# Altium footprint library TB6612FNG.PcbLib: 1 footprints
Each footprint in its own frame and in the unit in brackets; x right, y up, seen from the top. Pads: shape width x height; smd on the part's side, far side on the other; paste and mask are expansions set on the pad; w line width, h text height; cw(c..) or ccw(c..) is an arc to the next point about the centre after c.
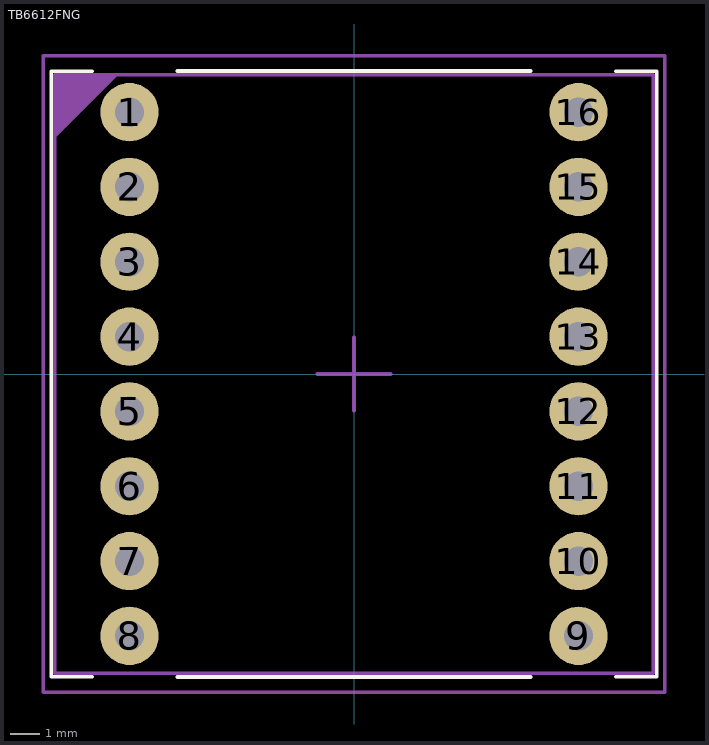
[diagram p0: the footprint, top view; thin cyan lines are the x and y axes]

## TB6612FNG [mm]
pads (16):
  round 1.98 hole 1: 1(-7.62,8.89) 2(-7.62,6.35) 3(-7.62,3.81) 4(-7.62,1.27) 5(-7.62,-1.27) 6(-7.62,-3.81) 7(-7.62,-6.35) 8(-7.62,-8.89) 9(7.62,-8.89) 10(7.62,-6.35) 11(7.62,-3.81) 12(7.62,-1.27) 13(7.62,1.27) 14(7.62,3.81) 15(7.62,6.35) 16(7.62,8.89)
Top Overlay:
  lines w0.127: -8.89,-10.28 -10.275,-10.28 -10.275,10.28 -8.89,10.28 ; -6,-10.285 6,-10.285 ; -6,10.285 6,10.285 ; 8.89,-10.28 10.275,-10.28 10.275,10.28 8.89,10.28
Top Assembly:
  region: -8,10.16 -10.16,10.16 -10.16,8
  lines w0.127: -10.16,-10.16 -10.16,10.16 10.16,10.16 10.16,-10.16 -10.16,-10.16
Top Courtyard (Mech15):
  lines w0.127: -1.25,0 1.25,0 ; 0,-1.25 0,1.25 ; -10.55,-10.8 -10.55,10.8 10.55,10.8 10.55,-10.8 -10.55,-10.8
3D body "TB6612FNG Module.STEP": height 6.12, standoff -5.99, extent -10.452,-10.28 10.452,10.7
